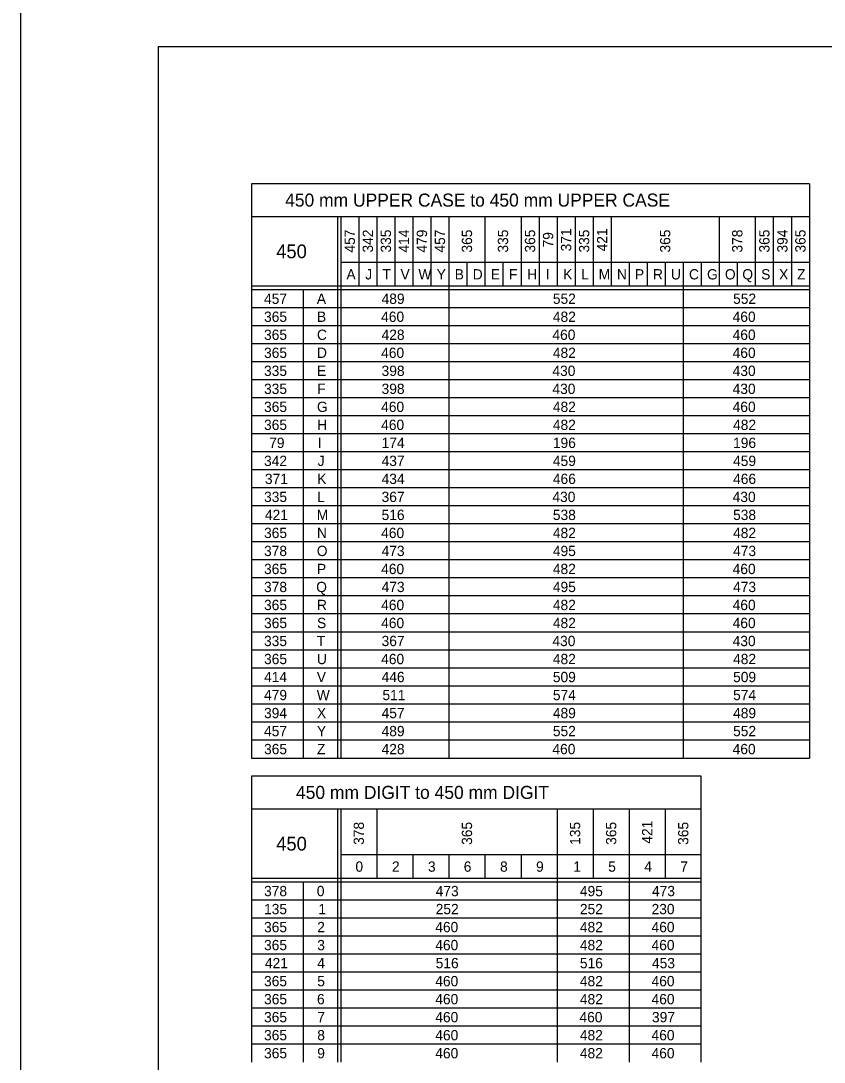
# Model space of a CAD drawing. Extents: x 637580 to 641849, y 297270 to 299646.
# Drawn here: x 637580.3 to 637814.3, y 297552.6 to 297856.1 of the extents above; entities that cross this region are included whole.
import ezdxf

# ---------------------------------------------------------------- set-up
doc = ezdxf.new("R2010")
doc.units = 0
for name, color, linetype in [('1', 7, 'Continuous'), ('2', 7, 'Continuous'), ('XCS-GRID-HVGL', 7, 'Continuous')]:
    doc.layers.add(name, color=color, linetype=linetype)

msp = doc.modelspace()

# ---------------------------------------------------------------- linework, layer by layer
at = {"layer": '1'}
for q in [(638406.31, 297848.63), (637620.31, 297284.63)]:
    msp.add_line((637620.31, 297848.63), q, dxfattribs=at)
at = {"layer": '2'}
for p, q in [((637810.01, 297808.63), (637647.51, 297808.63)), ((637647.51, 297808.63), (637647.51, 297641.25)), ((637810.01, 297808.63), (637810.01, 297641.25)), ((637647.51, 297799.13), (637810.01, 297799.13)), ((637672.51, 297799.13), (637672.51, 297641.25)), ((637673.51, 297799.13), (637673.51, 297641.25)), ((637678.76, 297799.13), (637678.76, 297778.75)), ((637684.01, 297799.13), (637684.01, 297778.75)), ((637689.26, 297799.13), (637689.26, 297778.75)), ((637694.51, 297799.13), (637694.51, 297778.75)), ((637699.76, 297799.13), (637699.76, 297778.75)), ((637705.01, 297799.13), (637705.01, 297641.25)), ((637715.51, 297799.13), (637715.51, 297778.75)), ((637726.01, 297799.13), (637726.01, 297778.75)), ((637731.26, 297799.13), (637731.26, 297778.75)), ((637736.51, 297799.13), (637736.51, 297778.75)), ((637741.76, 297799.13), (637741.76, 297778.75)), ((637747.01, 297799.13), (637747.01, 297778.75)), ((637752.26, 297799.13), (637752.26, 297778.75)), ((637783.76, 297799.13), (637783.76, 297778.75)), ((637794.26, 297799.13), (637794.26, 297778.75)), ((637799.51, 297799.13), (637799.51, 297778.75)), ((637804.76, 297799.13), (637804.76, 297778.75)), ((637673.51, 297785.75), (637810.01, 297785.75)), ((637710.26, 297785.75), (637710.26, 297778.75)), ((637720.76, 297785.75), (637720.76, 297778.75)), ((637757.51, 297785.75), (637757.51, 297778.75)), ((637762.76, 297785.75), (637762.76, 297778.75)), ((637768.01, 297785.75), (637768.01, 297778.75)), ((637768.01, 297785.75), (637768.01, 297778.75)), ((637773.26, 297785.75), (637773.26, 297641.25)), ((637778.51, 297785.75), (637778.51, 297778.75)), ((637789.01, 297785.75), (637789.01, 297778.75)), ((637810.01, 297778.75), (637647.51, 297778.75)), ((637810.01, 297777.75), (637647.51, 297777.75)), ((637662.51, 297777.75), (637662.51, 297641.25)), ((637810.01, 297772.5), (637647.51, 297772.5)), ((637810.01, 297767.25), (637647.51, 297767.25)), ((637810.01, 297762), (637647.51, 297762)), ((637810.01, 297756.75), (637647.51, 297756.75)), ((637810.01, 297751.5), (637647.51, 297751.5)), ((637810.01, 297746.25), (637647.51, 297746.25)), ((637810.01, 297741), (637647.51, 297741)), ((637810.01, 297735.75), (637647.51, 297735.75)), ((637810.01, 297730.5), (637647.51, 297730.5)), ((637810.01, 297725.25), (637647.51, 297725.25)), ((637810.01, 297720), (637647.51, 297720)), ((637810.01, 297714.75), (637647.51, 297714.75)), ((637810.01, 297709.5), (637647.51, 297709.5)), ((637810.01, 297704.25), (637647.51, 297704.25)), ((637810.01, 297699), (637647.51, 297699)), ((637810.01, 297693.75), (637647.51, 297693.75)), ((637810.01, 297688.5), (637647.51, 297688.5)), ((637810.01, 297683.25), (637647.51, 297683.25)), ((637810.01, 297678), (637647.51, 297678)), ((637810.01, 297672.75), (637647.51, 297672.75)), ((637810.01, 297667.5), (637647.51, 297667.5)), ((637810.01, 297662.25), (637647.51, 297662.25)), ((637810.01, 297657), (637647.51, 297657)), ((637810.01, 297651.75), (637647.51, 297651.75)), ((637810.01, 297646.5), (637647.51, 297646.5)), ((637647.51, 297641.25), (637647.51, 297641.25)), ((637647.51, 297641.25), (637810.01, 297641.25)), ((637778.51, 297636), (637647.51, 297636)), ((637647.51, 297636), (637647.51, 297552.63)), ((637778.51, 297552.63), (637778.51, 297636)), ((637647.51, 297626.5), (637778.51, 297626.5)), ((637672.51, 297626.5), (637672.51, 297552.63)), ((637673.51, 297626.5), (637673.51, 297552.63)), ((637684.01, 297626.5), (637684.01, 297606.13)), ((637736.51, 297626.5), (637736.51, 297552.63)), ((637747.01, 297626.5), (637747.01, 297606.13)), ((637757.51, 297626.5), (637757.51, 297552.63)), ((637768.01, 297626.5), (637768.01, 297606.13)), ((637673.51, 297613.13), (637778.51, 297613.13)), ((637694.51, 297613.13), (637694.51, 297606.13)), ((637705.01, 297613.13), (637705.01, 297606.13)), ((637715.51, 297613.13), (637715.51, 297606.13)), ((637726.01, 297613.13), (637726.01, 297606.13)), ((637778.51, 297606.13), (637647.51, 297606.13)), ((637778.51, 297605.13), (637647.51, 297605.13)), ((637662.51, 297605.13), (637662.51, 297552.63)), ((637778.51, 297599.88), (637647.51, 297599.88)), ((637778.51, 297594.63), (637647.51, 297594.63)), ((637778.51, 297589.38), (637647.51, 297589.38)), ((637778.51, 297584.13), (637647.51, 297584.13)), ((637778.51, 297578.88), (637647.51, 297578.88)), ((637778.51, 297573.63), (637647.51, 297573.63)), ((637778.51, 297568.38), (637647.51, 297568.38)), ((637778.51, 297563.13), (637647.51, 297563.13)), ((637778.51, 297557.88), (637647.51, 297557.88))]:
    msp.add_line(p, q, dxfattribs=at)
at = {"layer": 'XCS-GRID-HVGL'}
msp.add_lwpolyline([(637580.31, 297863.63), (638421.31, 297863.63), (638421.31, 297269.63), (637580.31, 297269.63)], close=True, dxfattribs=at)

# ---------------------------------------------------------------- texts
at = {"layer": '2'}
for s, height, p in [('450 mm UPPER CASE to 450 mm UPPER CASE', 3.8, (637657.3, 297801.98)), ('450', 4, (637654.7, 297786.94)), ('A', 3, (637675.16, 297780.75)), ('J', 3, (637680.64, 297780.75)), ('T', 3, (637685.64, 297780.75)), ('V', 3, (637690.91, 297780.75)), ('W', 3, (637696.13, 297780.75)), ('Y', 3, (637701.44, 297780.75)), ('B', 3, (637706.7, 297780.75)), ('D', 3, (637711.95, 297780.75)), ('E', 3, (637717.22, 297780.75)), ('F', 3, (637722.52, 297780.75)), ('H', 3, (637727.79, 297780.75)), ('I', 3, (637733.2, 297780.75)), ('K', 3, (637738.29, 297780.75)), ('L', 3, (637743.54, 297780.75)), ('M', 3, (637748.63, 297780.75)), ('N', 3, (637753.95, 297780.75)), ('P', 3, (637759.2, 297780.75)), ('R', 3, (637764.45, 297780.75)), ('U', 3, (637769.69, 297780.75)), ('C', 3, (637774.95, 297780.75)), ('G', 3, (637780.2, 297780.75)), ('O', 3, (637785.41, 297780.75)), ('Q', 3, (637790.48, 297780.75)), ('S', 3, (637795.97, 297780.75)), ('X', 3, (637801.19, 297780.75)), ('Z', 3, (637806.45, 297780.75)), ('457', 3, (637651.16, 297773.63)), ('A', 3, (637666.53, 297773.63)), ('489', 3, (637685.4, 297773.63)), ('552', 3, (637735.29, 297773.63)), ('552', 3, (637787.79, 297773.63)), ('365', 3, (637651.16, 297768.38)), ('B', 3, (637666.58, 297768.38)), ('460', 3, (637685.27, 297768.38)), ('482', 3, (637735.29, 297768.38)), ('460', 3, (637787.66, 297768.38)), ('365', 3, (637651.16, 297763.13)), ('C', 3, (637666.58, 297763.13)), ('428', 3, (637685.4, 297763.13)), ('460', 3, (637735.16, 297763.13)), ('460', 3, (637787.66, 297763.13)), ('365', 3, (637651.16, 297757.88)), ('460', 3, (637685.27, 297757.88)), ('482', 3, (637735.29, 297757.88)), ('460', 3, (637787.66, 297757.88)), ('D', 3, (637666.58, 297757.88)), ('335', 3, (637651.16, 297752.63)), ('E', 3, (637666.59, 297752.63)), ('398', 3, (637685.4, 297752.63)), ('430', 3, (637735.16, 297752.63)), ('430', 3, (637787.66, 297752.63)), ('335', 3, (637651.16, 297747.38)), ('F', 3, (637666.65, 297747.38)), ('398', 3, (637685.4, 297747.38)), ('430', 3, (637735.16, 297747.38)), ('430', 3, (637787.66, 297747.38)), ('365', 3, (637651.16, 297742.13)), ('G', 3, (637666.58, 297742.13)), ('460', 3, (637685.27, 297742.13)), ('482', 3, (637735.29, 297742.13)), ('460', 3, (637787.66, 297742.13)), ('365', 3, (637651.16, 297736.88)), ('H', 3, (637666.66, 297736.88)), ('460', 3, (637685.27, 297736.88)), ('482', 3, (637735.29, 297736.88)), ('482', 3, (637787.79, 297736.88)), ('79', 3, (637652.66, 297731.63)), ('I', 3, (637666.83, 297731.63)), ('174', 3, (637685.4, 297731.63)), ('196', 3, (637735.29, 297731.63)), ('196', 3, (637787.79, 297731.63)), ('342', 3, (637651.16, 297726.38)), ('J', 3, (637666.77, 297726.38)), ('437', 3, (637685.4, 297726.38)), ('459', 3, (637735.29, 297726.38)), ('459', 3, (637787.79, 297726.38)), ('371', 3, (637651.41, 297721.13)), ('K', 3, (637666.66, 297721.13)), ('434', 3, (637685.4, 297721.13)), ('466', 3, (637735.29, 297721.13)), ('466', 3, (637787.79, 297721.13)), ('335', 3, (637651.16, 297715.88)), ('L', 3, (637666.66, 297715.88)), ('367', 3, (637685.4, 297715.88)), ('430', 3, (637735.16, 297715.88)), ('430', 3, (637787.66, 297715.88)), ('421', 3, (637651.41, 297710.63)), ('M', 3, (637666.51, 297710.63)), ('516', 3, (637685.4, 297710.63)), ('538', 3, (637735.29, 297710.63)), ('538', 3, (637787.79, 297710.63)), ('365', 3, (637651.16, 297705.38)), ('N', 3, (637666.58, 297705.38)), ('460', 3, (637685.27, 297705.38)), ('482', 3, (637735.29, 297705.38)), ('482', 3, (637787.79, 297705.38)), ('378', 3, (637651.16, 297700.13)), ('O', 3, (637666.53, 297700.13)), ('473', 3, (637685.4, 297700.13)), ('495', 3, (637735.29, 297700.13)), ('473', 3, (637787.79, 297700.13)), ('365', 3, (637651.16, 297694.88)), ('P', 3, (637666.58, 297694.88)), ('460', 3, (637685.27, 297694.88)), ('482', 3, (637735.29, 297694.88)), ('460', 3, (637787.66, 297694.88)), ('378', 3, (637651.16, 297689.63)), ('Q', 3, (637666.35, 297689.63)), ('473', 3, (637685.4, 297689.63)), ('495', 3, (637735.29, 297689.63)), ('473', 3, (637787.79, 297689.63)), ('365', 3, (637651.16, 297684.38)), ('R', 3, (637666.58, 297684.38)), ('460', 3, (637685.27, 297684.38)), ('482', 3, (637735.29, 297684.38)), ('460', 3, (637787.66, 297684.38)), ('365', 3, (637651.16, 297679.13)), ('S', 3, (637666.59, 297679.13)), ('460', 3, (637685.27, 297679.13)), ('482', 3, (637735.29, 297679.13)), ('460', 3, (637787.66, 297679.13)), ('335', 3, (637651.16, 297673.88)), ('T', 3, (637666.52, 297673.88)), ('367', 3, (637685.4, 297673.88)), ('430', 3, (637735.16, 297673.88)), ('430', 3, (637787.66, 297673.88)), ('365', 3, (637651.16, 297668.63)), ('U', 3, (637666.57, 297668.63)), ('460', 3, (637685.27, 297668.63)), ('482', 3, (637735.29, 297668.63)), ('482', 3, (637787.79, 297668.63)), ('414', 3, (637651.16, 297663.38)), ('V', 3, (637666.53, 297663.38)), ('446', 3, (637685.4, 297663.38)), ('509', 3, (637735.29, 297663.38)), ('509', 3, (637787.79, 297663.38)), ('479', 3, (637651.16, 297658.13)), ('W', 3, (637666.51, 297658.13)), ('511', 3, (637685.65, 297658.13)), ('574', 3, (637735.29, 297658.13)), ('574', 3, (637787.79, 297658.13)), ('394', 3, (637651.16, 297652.88)), ('X', 3, (637666.57, 297652.88)), ('457', 3, (637685.4, 297652.88)), ('489', 3, (637735.29, 297652.88)), ('489', 3, (637787.79, 297652.88)), ('457', 3, (637651.16, 297647.63)), ('Y', 3, (637666.57, 297647.63)), ('489', 3, (637685.4, 297647.63)), ('552', 3, (637735.29, 297647.63)), ('552', 3, (637787.79, 297647.63)), ('365', 3, (637651.16, 297642.38)), ('Z', 3, (637666.58, 297642.38)), ('428', 3, (637685.4, 297642.38)), ('460', 3, (637735.16, 297642.38)), ('460', 3, (637787.66, 297642.38)), ('450 mm DIGIT to 450 mm DIGIT', 3.8, (637660.46, 297629.35)), ('450', 4, (637654.7, 297614.31)), ('0', 3, (637677.78, 297608.13)), ('2', 3, (637688.41, 297608.13)), ('3', 3, (637698.91, 297608.13)), ('6', 3, (637709.33, 297608.13)), ('8', 3, (637719.91, 297608.13)), ('9', 3, (637730.4, 297608.13)), ('1', 3, (637741.25, 297608.13)), ('5', 3, (637751.41, 297608.13)), ('4', 3, (637761.91, 297608.13)), ('7', 3, (637772.41, 297608.13)), ('378', 3, (637651.16, 297601)), ('0', 3, (637666.53, 297601)), ('473', 3, (637701.16, 297601)), ('495', 3, (637743.16, 297601)), ('473', 3, (637764.16, 297601)), ('135', 3, (637651.16, 297595.75)), ('1', 3, (637667, 297595.75)), ('252', 3, (637701.16, 297595.75)), ('252', 3, (637743.16, 297595.75)), ('230', 3, (637764.04, 297595.75)), ('365', 3, (637651.16, 297590.5)), ('2', 3, (637666.66, 297590.5)), ('460', 3, (637701.04, 297590.5)), ('482', 3, (637743.16, 297590.5)), ('460', 3, (637764.04, 297590.5)), ('365', 3, (637651.16, 297585.25)), ('3', 3, (637666.66, 297585.25)), ('460', 3, (637701.04, 297585.25)), ('482', 3, (637743.16, 297585.25)), ('460', 3, (637764.04, 297585.25)), ('421', 3, (637651.41, 297580)), ('4', 3, (637666.66, 297580)), ('516', 3, (637701.16, 297580)), ('516', 3, (637743.16, 297580)), ('453', 3, (637764.16, 297580)), ('365', 3, (637651.16, 297574.75)), ('5', 3, (637666.66, 297574.75)), ('460', 3, (637701.04, 297574.75)), ('482', 3, (637743.16, 297574.75)), ('460', 3, (637764.04, 297574.75)), ('365', 3, (637651.16, 297569.5)), ('6', 3, (637666.58, 297569.5)), ('460', 3, (637701.04, 297569.5)), ('482', 3, (637743.16, 297569.5)), ('460', 3, (637764.04, 297569.5)), ('365', 3, (637651.16, 297564.25)), ('7', 3, (637666.66, 297564.25)), ('460', 3, (637701.04, 297564.25)), ('460', 3, (637743.04, 297564.25)), ('397', 3, (637764.16, 297564.25)), ('365', 3, (637651.16, 297559)), ('8', 3, (637666.66, 297559)), ('460', 3, (637701.04, 297559)), ('482', 3, (637743.16, 297559)), ('460', 3, (637764.04, 297559)), ('365', 3, (637651.16, 297553.75)), ('9', 3, (637666.65, 297553.75)), ('460', 3, (637701.04, 297553.75)), ('482', 3, (637743.16, 297553.75)), ('460', 3, (637764.04, 297553.75))]:
    msp.add_text(s, height=height, dxfattribs=at).set_placement(p)
for s, p in [('457', (637677.64, 297788.59)), ('342', (637682.89, 297788.59)), ('335', (637688.14, 297788.59)), ('414', (637693.39, 297788.59)), ('479', (637698.64, 297788.58)), ('457', (637703.89, 297788.59)), ('365', (637711.76, 297788.59)), ('335', (637722.26, 297788.59)), ('365', (637730.14, 297788.59)), ('79', (637735.39, 297790.08)), ('371', (637740.64, 297788.93)), ('335', (637745.89, 297788.59)), ('421', (637751.14, 297788.93)), ('365', (637769.51, 297788.59)), ('378', (637790.51, 297788.59)), ('365', (637798.39, 297788.59)), ('394', (637803.64, 297788.59)), ('365', (637808.89, 297788.59)), ('378', (637680.26, 297615.96)), ('365', (637711.76, 297615.96)), ('135', (637743.26, 297615.96)), ('365', (637753.76, 297615.96)), ('421', (637764.26, 297616.31)), ('365', (637774.76, 297615.96))]:
    msp.add_text(s, height=3, rotation=90, dxfattribs=at).set_placement(p)

doc.saveas('drawing.dxf')
